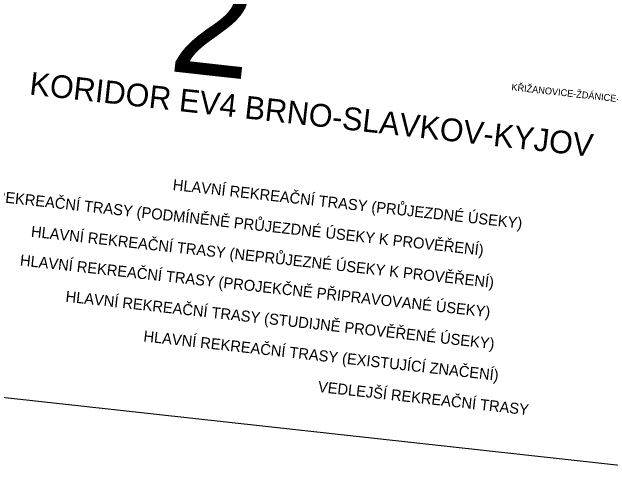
# Model space of a CAD drawing. Extents: x -678204 to -526855, y -1228851 to -1110393.
# Drawn here: x -587930 to -574848, y -1182415 to -1172295 of the extents above; entities that cross this region are included whole.
import ezdxf

# ---------------------------------------------------------------- set-up
doc = ezdxf.new("R2010")
doc.units = 0
for name, color, linetype in [('00_n_cyklo popisy ostatni', 7, 'Continuous'), ('00_n_legenda popisy', 7, 'Continuous'), ('00_n_legenda popisy_hlavni', 7, 'Continuous'), ('_HELP BIG', 7, 'Continuous')]:
    doc.layers.add(name, color=color, linetype=linetype)

msp = doc.modelspace()

# ---------------------------------------------------------------- linework, layer by layer
at = {"layer": '_HELP BIG'}
msp.add_lwpolyline([(-572713, -1182415), (-601001, -1179309), (-598788, -1159164), (-570501, -1162270)], close=True, dxfattribs=at)

# ---------------------------------------------------------------- texts
at = {"layer": '00_n_cyklo popisy ostatni'}
msp.add_text('KŘIŽANOVICE-ŽDÁNICE-KYJOV', height=150, rotation=353.6836, dxfattribs=at).set_placement((-577012, -1174007))
at = {"layer": '00_n_legenda popisy'}
for s, p in [('HLAVNÍ REKREAČNÍ TRASY (PRŮJEZDNÉ ÚSEKY) ', (-584421, -1176186)), ('HLAVNÍ REKREAČNÍ TRASY (PODMÍNĚNĚ PRŮJEZDNÉ ÚSEKY K PROVĚŘENÍ) ', (-589556, -1176299)), ('HLAVNÍ REKREAČNÍ TRASY (NEPRŮJEZNÉ ÚSEKY K PROVĚŘENÍ) ', (-587522, -1177206)), ('HLAVNÍ REKREAČNÍ TRASY (PROJEKČNĚ PŘIPRAVOVANÉ ÚSEKY) ', (-587763, -1177834)), ('HLAVNÍ REKREAČNÍ TRASY (STUDIJNĚ PROVĚŘENÉ ÚSEKY) ', (-586766, -1178626)), ('HLAVNÍ REKREAČNÍ TRASY (EXISTUJÍCÍ ZNAČENÍ) ', (-585062, -1179495)), ('VEDLEJŠÍ REKREAČNÍ TRASY ', (-581246, -1180599))]:
    msp.add_text(s, height=240, rotation=353.6836, dxfattribs=at).set_placement(p)
at = {"layer": '00_n_legenda popisy_hlavni'}
msp.add_text('KORIDOR EV4 BRNO-SLAVKOV-KYJOV', height=497.66, rotation=353.6836, dxfattribs=at).set_placement((-587562, -1174098))
at = {"layer": '_HELP BIG'}
msp.add_text('2', height=2400, rotation=353.6836, dxfattribs=at).set_placement((-584538, -1173581))

doc.saveas('drawing.dxf')
